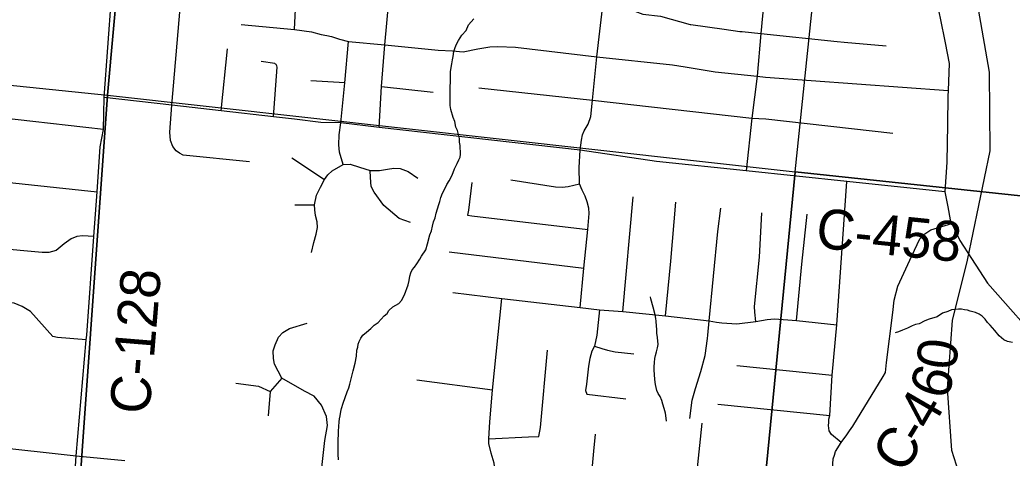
# Model space of a CAD drawing. Extents: x 0 to 34, y -2 to 22.
# Drawn here: x 3.329 to 4.743, y 19.479 to 20.104 of the extents above; entities that cross this region are included whole.
import ezdxf

# ---------------------------------------------------------------- set-up
doc = ezdxf.new("R2010")
doc.units = 0
for name, color, linetype in [('Default', 7, 'Continuous'), ('GM_X_County_Road', 7, 'Continuous'), ('GM_X_County_Road_Text', 7, 'Continuous'), ('GM_X_Minor_River', 7, 'Continuous'), ('GM_X_Rail_Line', 7, 'Continuous'), ('GM_X_Section', 7, 'Continuous'), ('GM_X_State_Route', 7, 'Continuous'), ('GM_X_Township_Road', 7, 'Continuous')]:
    doc.layers.add(name, color=color, linetype=linetype)

msp = doc.modelspace()

# ---------------------------------------------------------------- linework, layer by layer
at = {"layer": 'Default'}
for points in [[(3.5359, 20.9), (2.5176, 20.9), (2.4387, 20.1012), (3.4541, 19.9967)], [(4.5319, 20.9), (3.5359, 20.9), (3.4541, 19.9967), (4.4338, 19.8873), (4.539, 20.8993)]]:
    msp.add_lwpolyline(points, close=True, dxfattribs=at)
at = {"layer": 'GM_X_County_Road'}
msp.add_line((3.4093, 19.4828), (3.4788, 19.4761), dxfattribs=at)
for points in [[(3.4093, 19.4828), (3.4238, 19.6478), (3.4244, 19.6548), (3.4345, 19.795), (3.4391, 19.8586), (3.4438, 19.9231), (3.4481, 19.9478), (3.4491, 19.9932), (3.4599, 20.136), (3.4715, 20.2724), (3.4928, 20.4968)], [(4.647, 19.8589), (4.5072, 19.8736), (4.3638, 19.8887), (4.2363, 19.9022), (4.1275, 19.9182), (3.8412, 19.9505), (3.7864, 19.957), (3.7577, 19.9577), (3.7203, 19.9621), (3.6903, 19.9655), (3.6159, 19.974), (3.5459, 19.9821), (3.4491, 19.9932)], [(4.5112, 19.5184), (4.5159, 19.5251), (4.5591, 19.5959), (4.5623, 19.6015), (4.5639, 19.6155), (4.5727, 19.687), (4.5744, 19.7044), (4.58, 19.7244), (4.6, 19.7678), (4.611, 19.7917), (4.6181, 19.7991), (4.627, 19.8045), (4.6567, 19.8139)], [(2.3798, 19.5908), (2.4889, 19.5795), (2.6752, 19.5607), (2.9711, 19.5296), (3.1409, 19.5124), (3.1645, 19.51), (3.4093, 19.4828)], [(4.4862, 19.4569), (4.4879, 19.4786), (4.4894, 19.4836), (4.4911, 19.4889), (4.4989, 19.5016), (4.507, 19.5125), (4.5112, 19.5184)], [(3.3764, 19.0222), (3.3785, 19.0257), (3.382, 19.0419), (3.3907, 19.1924), (3.3925, 19.2247), (3.4045, 19.4092), (3.4093, 19.4828)]]:
    msp.add_lwpolyline(points, dxfattribs=at)
at = {"layer": 'GM_X_Minor_River'}
for points in [[(3.7994, 19.585), (3.8016, 19.5944), (3.8042, 19.6038), (3.8069, 19.6147), (3.8087, 19.6246), (3.8094, 19.6333), (3.8107, 19.6374), (3.8112, 19.6416), (3.8125, 19.6457), (3.8149, 19.6502), (3.8177, 19.6546), (3.8228, 19.659), (3.8291, 19.6641), (3.8338, 19.6689), (3.8396, 19.6725), (3.8479, 19.6821), (3.8522, 19.6854), (3.8546, 19.6899), (3.8605, 19.695), (3.869, 19.6996), (3.873, 19.704), (3.877, 19.7119), (3.8821, 19.7262), (3.8838, 19.7326), (3.8848, 19.7386), (3.8861, 19.7435), (3.8878, 19.7476), (3.8913, 19.7517), (3.8945, 19.7561), (3.8989, 19.7628), (3.9013, 19.7673), (3.9077, 19.7762), (3.9099, 19.7849), (3.9134, 19.7977), (3.9155, 19.8033), (3.9169, 19.8097), (3.9186, 19.8161), (3.9207, 19.8217), (3.9224, 19.8285), (3.9259, 19.8406), (3.9272, 19.8451), (3.9289, 19.8507), (3.9314, 19.8571), (3.9339, 19.8623), (3.9375, 19.8691), (3.9407, 19.8743), (3.9448, 19.8825), (3.9485, 19.8915), (3.9519, 19.8993), (3.9543, 19.9042), (3.9563, 19.9083), (3.9569, 19.9125), (3.9565, 19.9247), (3.9556, 19.9296), (3.9554, 19.935), (3.9527, 19.9461), (3.9502, 19.9511), (3.9486, 19.9591), (3.9465, 19.9649), (3.9431, 19.976), (3.9422, 19.9818), (3.9421, 19.9901), (3.9421, 20.0012), (3.9428, 20.0224), (3.9427, 20.0297), (3.9437, 20.0357), (3.9446, 20.041), (3.9456, 20.0467), (3.9465, 20.0516), (3.9475, 20.0588), (3.9488, 20.0629), (3.9508, 20.0681), (3.9541, 20.0745), (3.9589, 20.0819), (3.9648, 20.0886), (3.9685, 20.0968), (3.9757, 20.1053)], [(4.2502, 19.5319), (4.2499, 19.5363), (4.249, 19.5435), (4.2469, 19.5501), (4.2452, 19.5562), (4.2435, 19.5616), (4.2411, 19.5674), (4.2386, 19.5717), (4.2364, 19.5759), (4.2348, 19.5843), (4.2339, 19.5916), (4.2334, 19.5984), (4.2329, 19.6049), (4.2327, 19.6095), (4.2332, 19.6155), (4.2338, 19.6212), (4.2347, 19.6258), (4.236, 19.6307), (4.2374, 19.6367), (4.2383, 19.6412), (4.2375, 19.6515), (4.2366, 19.6576), (4.2364, 19.6633), (4.2362, 19.6675), (4.2357, 19.6744), (4.235, 19.6786), (4.2341, 19.6836), (4.2314, 19.6947), (4.228, 19.7066), (4.2273, 19.7092)], [(4.743, 19.6443), (4.7362, 19.6456), (4.7306, 19.6481), (4.724, 19.6537), (4.7178, 19.6611), (4.7116, 19.6689), (4.7075, 19.6729), (4.7043, 19.6772), (4.6999, 19.6819), (4.6958, 19.6847), (4.6906, 19.6871), (4.683, 19.6889), (4.6789, 19.6902), (4.6747, 19.6907), (4.6706, 19.6916), (4.6664, 19.6918), (4.6565, 19.6906), (4.6511, 19.6885), (4.6434, 19.6861), (4.6357, 19.6807), (4.6245, 19.6776), (4.6184, 19.6752), (4.6103, 19.6709), (4.6049, 19.6696), (4.6003, 19.6678), (4.5937, 19.6646), (4.5864, 19.6619), (4.5806, 19.6594), (4.576, 19.658)], [(3.7831, 19.4772), (3.7826, 19.4852), (3.7824, 19.4901), (3.7826, 19.4943), (3.7824, 19.5015), (3.783, 19.5179), (3.7836, 19.5247), (3.7842, 19.5311), (3.7844, 19.5353), (3.7853, 19.5398), (3.7863, 19.5459), (3.7875, 19.5504), (3.7897, 19.5576), (3.7956, 19.5741), (3.7977, 19.5797), (3.7994, 19.585)]]:
    msp.add_lwpolyline(points, dxfattribs=at)
at = {"layer": 'GM_X_Rail_Line'}
msp.add_lwpolyline([(4.6999, 19.3545), (4.657, 19.4903), (4.6508, 19.5786), (4.6577, 19.6755), (4.679, 19.7614), (4.7115, 19.9173), (4.7104, 20.0292), (4.6947, 20.1189), (4.6732, 20.1949), (4.6217, 20.3034), (4.5682, 20.4079), (4.536, 20.4795), (4.4891, 20.5622), (4.454, 20.6117), (4.3411, 20.73), (4.2485, 20.8379), (4.2078, 20.9)], dxfattribs=at)
at = {"layer": 'GM_X_Section'}
for points in [[(4.539, 20.8993), (5.5442, 20.7879), (5.4475, 19.8207), (4.8002, 19.892), (4.7992, 19.8486), (4.4338, 19.8873)], [(3.4541, 19.9967), (3.3818, 18.9832), (2.3398, 19.083), (2.4387, 20.1012)], [(3.4541, 19.9967), (4.4338, 19.8873), (4.3356, 18.8839), (3.3818, 18.9832)], [(5.4475, 19.8207), (5.4431, 19.7776), (5.3451, 18.7715), (4.3356, 18.8839), (4.4338, 19.8873), (4.7992, 19.8486), (4.8002, 19.892)]]:
    msp.add_lwpolyline(points, close=True, dxfattribs=at)
at = {"layer": 'GM_X_State_Route'}
for points in [[(4.5527, 20.4429), (4.5542, 20.4271), (4.5557, 20.3915), (4.5582, 20.3702), (4.5643, 20.353), (4.5689, 20.3403), (4.5862, 20.3024), (4.605, 20.2636), (4.6089, 20.2525), (4.6287, 20.1597), (4.64, 20.1064), (4.6474, 20.0712), (4.6532, 20.0414), (4.6516, 20.0031), (4.6513, 19.9951), (4.6505, 19.9548)], [(4.6505, 19.9548), (4.6495, 19.901), (4.647, 19.8589), (4.651, 19.8375), (4.6544, 19.8189), (4.6567, 19.8139), (4.6681, 19.7893), (4.6846, 19.7639)], [(4.6846, 19.7639), (4.7076, 19.7288), (4.7914, 19.6338), (4.8098, 19.6136)]]:
    msp.add_lwpolyline(points, dxfattribs=at)
at = {"layer": 'GM_X_Township_Road'}
for p, q in [((3.6159, 19.974), (3.625, 20.0627)), ((3.7919, 20.014), (3.7437, 20.0171)), ((3.8444, 20.0087), (3.918, 20.0009)), ((3.7164, 19.9074), (3.763, 19.8765)), ((4.188, 19.6885), (4.2029, 19.8518)), ((3.7208, 19.8405), (3.749, 19.8401)), ((3.9409, 19.7734), (4.1327, 19.7503)), ((4.3504, 19.6113), (4.4865, 19.5977)), ((4.0024, 19.5765), (3.8947, 19.5907)), ((4.3232, 19.5565), (4.4828, 19.54))]:
    msp.add_line(p, q, dxfattribs=at)
for points in [[(3.8412, 19.9505), (3.8444, 20.0087), (3.8491, 20.068), (3.855, 20.1298), (3.8598, 20.1915), (3.8609, 20.2055), (3.8611, 20.2134), (3.858, 20.2203), (3.8504, 20.235), (3.8456, 20.2429), (3.8437, 20.2502), (3.8573, 20.4568), (3.8701, 20.621)], [(3.7203, 20.0901), (3.723, 20.1386), (3.7293, 20.2013)], [(3.6564, 19.9016), (3.5617, 19.9109), (3.5565, 19.9138), (3.5517, 19.9173), (3.5473, 19.9232), (3.5438, 19.932), (3.5427, 19.9438), (3.5459, 19.9821), (3.5624, 20.1761)], [(4.1272, 19.6942), (4.1327, 19.7503), (4.1381, 19.8053), (4.1403, 19.828), (4.1397, 19.8356), (4.1374, 19.8446), (4.1345, 19.8526), (4.1304, 19.8612), (4.1264, 19.8703), (4.1259, 19.8933), (4.1275, 19.9182), (4.1294, 19.9322), (4.1307, 19.9402), (4.1328, 19.9458), (4.1386, 19.9551), (4.1423, 19.9659), (4.1448, 19.9892), (4.1512, 20.0513), (4.1607, 20.133)], [(4.1311, 20.1363), (4.1607, 20.133), (4.1678, 20.1323), (4.1777, 20.1302), (4.1848, 20.1276), (4.1937, 20.1223), (4.2014, 20.1174), (4.2166, 20.1121), (4.2417, 20.109), (4.284, 20.0971), (4.285, 20.097)], [(4.3896, 20.1329), (4.3873, 20.1096), (4.3849, 20.0844), (4.3796, 20.0234), (4.3718, 19.9637), (4.3638, 19.8887)], [(3.6444, 20.097), (3.7203, 20.0901), (3.7446, 20.0866), (3.7586, 20.0831), (3.7663, 20.0814), (3.7733, 20.0799), (3.7847, 20.0764), (3.7973, 20.0729), (3.8491, 20.068), (3.9252, 20.0607), (3.9454, 20.0596), (3.9609, 20.0584), (3.9816, 20.0624), (3.9988, 20.0652), (4.0101, 20.0658), (4.0351, 20.0649), (4.1512, 20.0513), (4.2589, 20.0397), (4.2768, 20.0368), (4.3197, 20.0298), (4.3796, 20.0234), (4.3915, 20.0222), (4.6516, 20.0031)], [(4.285, 20.097), (4.3323, 20.0904), (4.355, 20.0873)], [(4.355, 20.0873), (4.358, 20.087), (4.3849, 20.0844), (4.4936, 20.073)], [(3.7864, 19.957), (3.7919, 20.014), (3.7973, 20.0729)], [(4.4936, 20.073), (4.5035, 20.0719), (4.5631, 20.067)], [(3.6903, 19.9655), (3.6955, 20.0362), (3.6952, 20.0384), (3.6944, 20.04), (3.6935, 20.0409), (3.6922, 20.0416), (3.673, 20.0445)], [(3.9828, 20.0068), (4.1448, 19.9892), (4.3718, 19.9637), (4.3916, 19.9626), (4.5727, 19.9426)], [(3.4481, 19.9478), (3.2971, 19.9647), (3.1945, 19.9751), (3.0101, 19.9946), (2.9863, 19.9958), (2.9649, 19.9918)], [(3.7898, 19.8976), (3.7843, 19.9152), (3.7835, 19.9256), (3.7841, 19.9401), (3.7864, 19.957)], [(3.7448, 19.7723), (3.7481, 19.7867), (3.7515, 19.7987), (3.7534, 19.8081), (3.7525, 19.8162), (3.7504, 19.8252), (3.7492, 19.8334), (3.749, 19.8401), (3.7516, 19.8539), (3.7574, 19.8655), (3.763, 19.8765), (3.7678, 19.883), (3.7741, 19.8888), (3.7898, 19.8976), (3.7996, 19.8984), (3.8128, 19.8938), (3.8283, 19.889), (3.8414, 19.8892), (3.8529, 19.8913), (3.8619, 19.8924), (3.8709, 19.892), (3.8822, 19.8878), (3.8962, 19.8781)], [(3.8856, 19.815), (3.8695, 19.8206), (3.8477, 19.8395), (3.8337, 19.8583), (3.8297, 19.8666), (3.8287, 19.8794), (3.8283, 19.889)], [(3.1435, 19.7956), (3.1444, 19.8106), (3.1465, 19.819), (3.1513, 19.8337), (3.1673, 19.8742), (3.1713, 19.879), (3.1782, 19.8815), (3.187, 19.8846), (3.2029, 19.8841), (3.4391, 19.8586)], [(4.0288, 19.8758), (4.0923, 19.8659), (4.1019, 19.8656), (4.1104, 19.8666), (4.1264, 19.8703)], [(3.9731, 19.8721), (3.9682, 19.8328), (3.9668, 19.8254), (3.9728, 19.8244), (4.1381, 19.8053)], [(4.4989, 19.5016), (4.4853, 19.5129), (4.4822, 19.5185), (4.4811, 19.526), (4.4814, 19.5303), (4.4817, 19.5351), (4.4828, 19.54), (4.4865, 19.5977), (4.4928, 19.6692), (4.5072, 19.8736)], [(4.2489, 19.6823), (4.2565, 19.7599), (4.2637, 19.8439)], [(4.309, 19.6548), (4.3109, 19.6751), (4.3233, 19.8024), (4.3279, 19.8356)], [(4.3775, 19.6741), (4.376, 19.6875), (4.3757, 19.6953), (4.3826, 19.7657), (4.3861, 19.8287)], [(4.4356, 19.6757), (4.4433, 19.7559), (4.4507, 19.8269)], [(3.4345, 19.795), (3.4186, 19.7959), (3.4105, 19.7953), (3.4024, 19.792), (3.3924, 19.7847), (3.3807, 19.7753), (3.3706, 19.7724), (3.3612, 19.7723), (3.2256, 19.7846), (3.2226, 19.785)], [(3.4238, 19.6478), (3.3826, 19.6512), (3.3762, 19.6529), (3.3445, 19.6885), (3.3325, 19.6954), (3.3211, 19.7002), (3.135, 19.7202), (3.0982, 19.7207), (3.0555, 19.7199), (3.0347, 19.721)], [(3.946, 19.7155), (4.0156, 19.707), (4.1272, 19.6942), (4.155, 19.6905), (4.188, 19.6885), (4.2489, 19.6823), (4.3109, 19.6751), (4.3217, 19.673), (4.329, 19.6722), (4.3503, 19.6708), (4.3775, 19.6741), (4.3937, 19.6768), (4.4043, 19.6779), (4.4356, 19.6757), (4.4928, 19.6692)], [(4.0026, 19.4257), (4.0061, 19.4593), (4.0047, 19.4725), (4.0007, 19.4867), (3.9974, 19.5002), (3.997, 19.5068), (3.9983, 19.5233), (3.9987, 19.5314), (4.0024, 19.5765), (4.0156, 19.707)], [(4.155, 19.6905), (4.1509, 19.6546), (4.1478, 19.6392), (4.1439, 19.6318), (4.1412, 19.6214), (4.1391, 19.6103), (4.1362, 19.585), (4.1347, 19.576), (4.1366, 19.5706), (4.1926, 19.5639)], [(3.7574, 19.4492), (3.7634, 19.5046), (3.7674, 19.5258), (3.7662, 19.5389), (3.7591, 19.555), (3.7485, 19.5676), (3.7348, 19.575), (3.7023, 19.5935), (3.692, 19.6131), (3.6904, 19.6215), (3.6899, 19.6322), (3.6927, 19.6411), (3.6975, 19.6517), (3.7039, 19.6585), (3.7131, 19.6642), (3.7384, 19.6715)], [(4.2836, 19.5359), (4.2867, 19.5619), (4.2918, 19.5785), (4.2993, 19.6029), (4.3054, 19.6256), (4.3085, 19.6497), (4.309, 19.6548)], [(4.1478, 19.6392), (4.1583, 19.6356), (4.1664, 19.6334), (4.1771, 19.631), (4.2038, 19.6282)], [(3.997, 19.5068), (4.0536, 19.5098), (4.0686, 19.5105), (4.0707, 19.5231), (4.0808, 19.6331)], [(3.7023, 19.5935), (3.6857, 19.5745), (3.683, 19.5395)], [(3.637, 19.5864), (3.6692, 19.5818), (3.6857, 19.5745)], [(4.2871, 19.3945), (4.2935, 19.4566), (4.301, 19.5292)], [(4.1461, 19.4103), (4.1475, 19.4216), (4.1467, 19.4272), (4.1429, 19.4346), (4.1403, 19.4411), (4.1386, 19.446), (4.139, 19.4508), (4.1403, 19.4553), (4.1445, 19.4633), (4.1469, 19.4896), (4.1492, 19.5134)]]:
    msp.add_lwpolyline(points, dxfattribs=at)

# ---------------------------------------------------------------- texts
at = {"layer": 'GM_X_County_Road_Text'}
for s, height, rotation, p in [('C-458', 0.05682, 354.2285, (4.4616, 19.7795)), ('C-128', 0.05682, 85.3275, (3.5136, 19.5409)), ('0', 0.0568, 82.174, (4.6617, 19.6034)), ('6', 0.0568, 73.6665, (4.6499, 19.5608)), ('4', 0.0568, 59.904, (4.6265, 19.5169)), ('C', 0.0568, 57.3281, (4.5877, 19.4553)), ('-', 0.0568, 58.4922, (4.6135, 19.4957))]:
    msp.add_text(s, height=height, rotation=rotation, dxfattribs=at).set_placement(p)

doc.saveas('drawing.dxf')
